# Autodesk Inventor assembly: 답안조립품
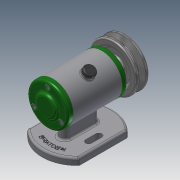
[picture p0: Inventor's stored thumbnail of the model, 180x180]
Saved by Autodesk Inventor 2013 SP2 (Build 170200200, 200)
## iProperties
Created: 2022-02
Part Number: 답안조립품
Document SubType Name: Assembly
Designer: a
Author: a
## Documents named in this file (14)
- C:\Users\a\Desktop\720206V1015\답안조립품.iam
- C:\Users\a\Desktop\720206V1015\본체.ipt
- C:\Users\a\Desktop\720206V1015\V벨트풀리.ipt
- C:\Users\a\Desktop\720206V1015\고무 캡.ipt
- C:\Users\a\Desktop\720206V1015\너트 M8.ipt
- C:\Users\a\Desktop\720206V1015\뒤커버.ipt
- C:\Users\a\Desktop\720206V1015\베어링 6002.ipt
- C:\Users\a\Desktop\720206V1015\볼트 M4 x 10.ipt
- C:\Users\a\Desktop\720206V1015\스프링와셔 8.ipt
- C:\Users\a\Desktop\720206V1015\앞커버.ipt
- C:\Users\a\Desktop\720206V1015\오일 실 15 x 25 x 7.ipt
- C:\Users\a\Desktop\720206V1015\축.ipt
- C:\Users\a\Desktop\720206V1015\키 3 x 3 x 12.ipt
- C:\Users\a\Desktop\720206V1015\평와셔 8 x 17.ipt
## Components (2 placed, 2 different names)
1. V벨트풀리:1
2. 고무 캡:1
